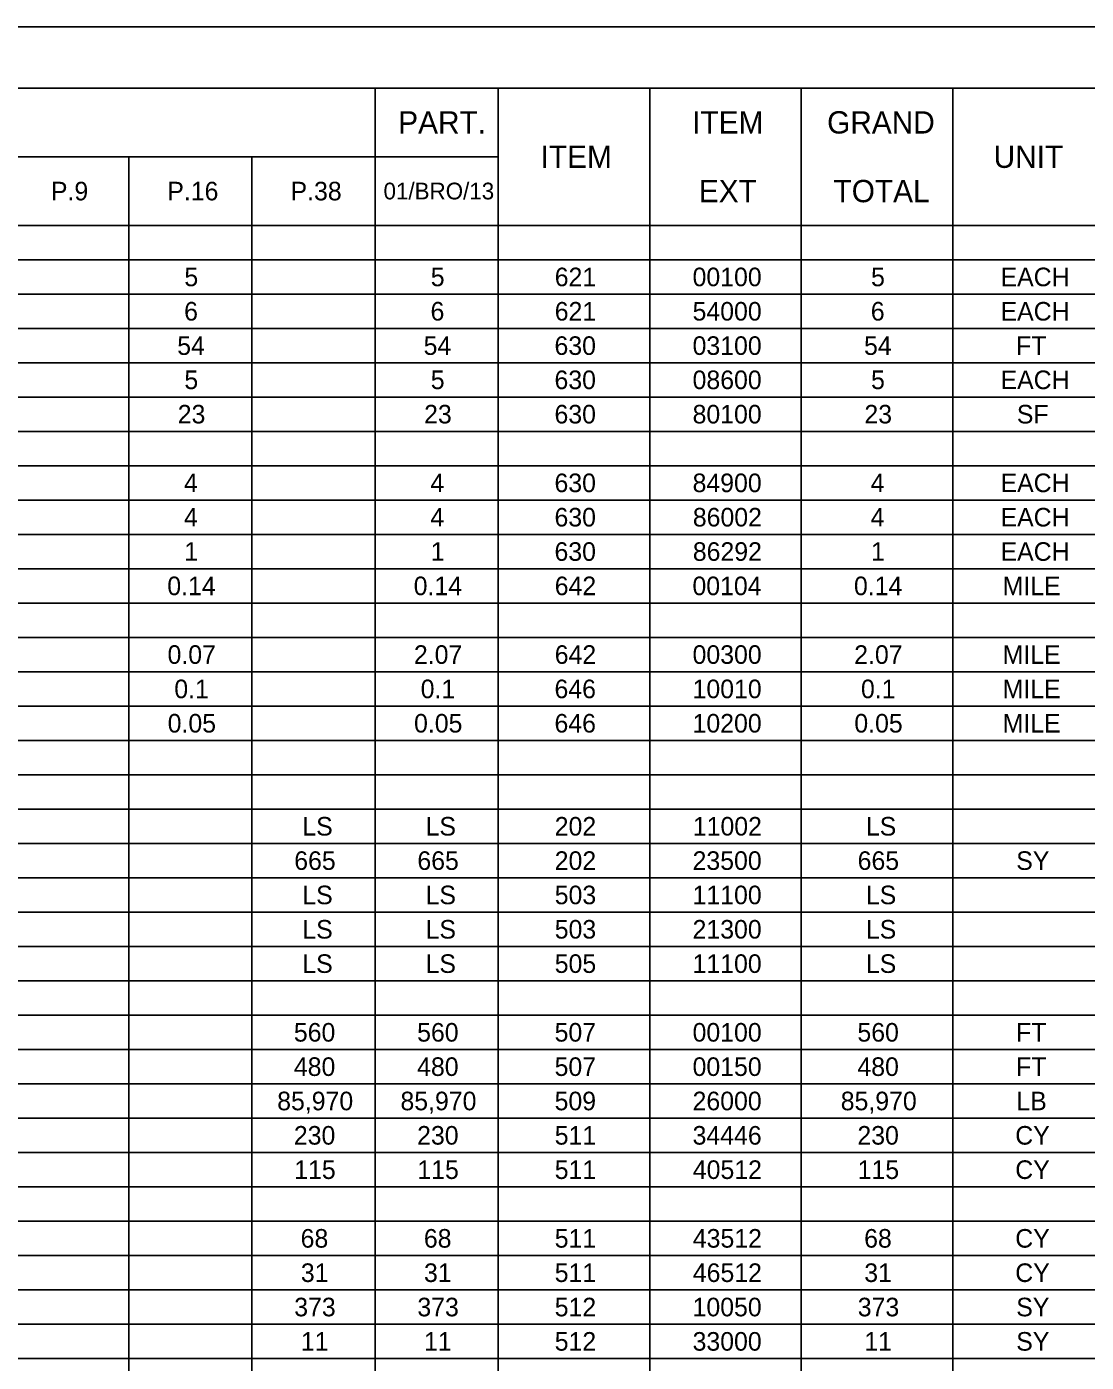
# Model space of a CAD drawing. Extents: x 0 to 34, y 0 to 22.
# Drawn here: x 8.71 to 17.35, y 11.11 to 22 of the extents above; entities that cross this region are included whole.
import ezdxf

# ---------------------------------------------------------------- set-up
doc = ezdxf.new("R2010")
doc.units = 0
for name, color, linetype in [('Default', 7, 'Continuous'), ('SH_Border', 7, 'Continuous'), ('SH_Cut_Line', 7, 'Continuous')]:
    doc.layers.add(name, color=color, linetype=linetype)

msp = doc.modelspace()

# ---------------------------------------------------------------- linework, layer by layer
at = {"layer": 'Default'}
for p, q in [((1.5, 21.5), (32, 21.5)), ((11.546, 21.5), (11.546, 0.502)), ((12.55, 21.5), (12.55, 0.502)), ((13.786, 21.5), (13.786, 0.502)), ((15.021, 21.5), (15.021, 0.502)), ((16.256, 21.5), (16.256, 0.502)), ((1.5, 20.94), (12.55, 20.94)), ((9.537, 20.94), (9.537, 0.502)), ((10.541, 20.94), (10.541, 0.502)), ((1.5, 20.38), (32, 20.38)), ((1.5, 20.1), (32, 20.1)), ((1.5, 19.82), (32, 19.82)), ((1.5, 19.54), (32, 19.54)), ((1.5, 19.26), (32, 19.26)), ((1.5, 18.98), (32, 18.98)), ((1.5, 18.7), (32, 18.7)), ((1.5, 18.42), (32, 18.42)), ((1.5, 18.14), (32, 18.14)), ((1.5, 17.86), (32, 17.86)), ((1.5, 17.58), (32, 17.58)), ((1.5, 17.3), (32, 17.3)), ((1.5, 17.021), (32, 17.021)), ((1.5, 16.741), (32, 16.741)), ((1.5, 16.461), (32, 16.461)), ((1.5, 16.181), (32, 16.181)), ((1.5, 15.901), (32, 15.901)), ((1.5, 15.621), (32, 15.621)), ((1.5, 15.341), (32, 15.341)), ((1.5, 15.061), (32, 15.061)), ((1.5, 14.781), (32, 14.781)), ((1.5, 14.501), (32, 14.501)), ((1.5, 14.221), (32, 14.221)), ((1.5, 13.941), (32, 13.941)), ((1.5, 13.661), (32, 13.661)), ((1.5, 13.381), (32, 13.381)), ((1.5, 13.101), (32, 13.101)), ((1.5, 12.821), (32, 12.821)), ((1.5, 12.541), (32, 12.541)), ((1.5, 12.261), (32, 12.261)), ((1.5, 11.981), (32, 11.981)), ((1.5, 11.701), (32, 11.701)), ((1.5, 11.421), (32, 11.421)), ((1.5, 11.141), (32, 11.141))]:
    msp.add_line(p, q, dxfattribs=at)
at = {"layer": 'SH_Border'}
msp.add_lwpolyline([(1.5, 21.5), (33.5, 21.5), (33.5, 0.5), (1.5, 0.5)], close=True, dxfattribs=at)
at = {"layer": 'SH_Cut_Line'}
msp.add_lwpolyline([(0, 0), (34, 0), (34, 22), (0, 22)], close=True, dxfattribs=at)

# ---------------------------------------------------------------- texts
at = {"layer": 'Default'}
for s, height, p in [('PART.', 0.1818, (11.735, 21.129)), ('ITEM', 0.1818, (14.132, 21.129)), ('GRAND', 0.1818, (15.232, 21.129)), ('ITEM', 0.1818, (12.896, 20.849)), ('UNIT', 0.1818, (16.59, 20.849)), ('P.9', 0.1515, (8.903, 20.584)), ('P.16', 0.1515, (9.852, 20.584)), ('P.38', 0.1515, (10.857, 20.584)), ('01/BRO/13', 0.1364, (11.615, 20.592)), ('EXT', 0.1818, (14.186, 20.569)), ('TOTAL', 0.1818, (15.284, 20.569)), ('621', 0.1515, (13.011, 19.884)), ('00100', 0.1515, (14.135, 19.884)), ('EACH', 0.1515, (16.646, 19.884)), ('5', 0.152, (9.991, 19.884)), ('5', 0.152, (12, 19.884)), ('5', 0.152, (15.59, 19.884)), ('6', 0.152, (9.989, 19.604)), ('6', 0.152, (11.998, 19.604)), ('621', 0.1515, (13.011, 19.604)), ('54000', 0.1515, (14.135, 19.604)), ('6', 0.152, (15.588, 19.604)), ('EACH', 0.1515, (16.646, 19.604)), ('54', 0.1515, (9.933, 19.324)), ('54', 0.1515, (11.942, 19.324)), ('630', 0.1515, (13.009, 19.324)), ('03100', 0.1515, (14.135, 19.324)), ('54', 0.1515, (15.533, 19.324)), ('FT', 0.1515, (16.773, 19.324)), ('5', 0.152, (9.991, 19.045)), ('5', 0.152, (12, 19.045)), ('630', 0.1515, (13.009, 19.045)), ('08600', 0.1515, (14.135, 19.045)), ('5', 0.152, (15.59, 19.045)), ('EACH', 0.1515, (16.646, 19.045)), ('23', 0.1515, (9.937, 18.765)), ('23', 0.1515, (11.946, 18.765)), ('630', 0.1515, (13.009, 18.765)), ('80100', 0.1515, (14.135, 18.765)), ('23', 0.1515, (15.536, 18.765)), ('SF', 0.1515, (16.779, 18.765)), ('4', 0.152, (9.988, 18.205)), ('4', 0.152, (11.997, 18.205)), ('630', 0.1515, (13.009, 18.205)), ('84900', 0.1515, (14.135, 18.205)), ('4', 0.152, (15.587, 18.205)), ('EACH', 0.1515, (16.646, 18.205)), ('630', 0.1515, (13.009, 17.925)), ('86002', 0.1515, (14.137, 17.925)), ('EACH', 0.1515, (16.646, 17.925)), ('4', 0.152, (9.988, 17.925)), ('4', 0.152, (11.997, 17.925)), ('4', 0.152, (15.587, 17.925)), ('1', 0.152, (9.99, 17.645)), ('1', 0.152, (12, 17.645)), ('630', 0.1515, (13.009, 17.645)), ('86292', 0.1515, (14.137, 17.645)), ('1', 0.152, (15.59, 17.645)), ('EACH', 0.1515, (16.646, 17.645)), ('0.14', 0.1515, (9.852, 17.365)), ('0.14', 0.1515, (11.861, 17.365)), ('642', 0.1515, (13.011, 17.365)), ('00104', 0.1515, (14.134, 17.365)), ('0.14', 0.1515, (15.451, 17.365)), ('MILE', 0.1515, (16.663, 17.365)), ('0.07', 0.1515, (9.854, 16.805)), ('2.07', 0.1515, (11.863, 16.805)), ('642', 0.1515, (13.011, 16.805)), ('00300', 0.1515, (14.135, 16.805)), ('2.07', 0.1515, (15.453, 16.805)), ('MILE', 0.1515, (16.663, 16.805)), ('0.1', 0.1515, (9.909, 16.525)), ('0.1', 0.1515, (11.918, 16.525)), ('646', 0.1515, (13.009, 16.525)), ('10010', 0.1515, (14.135, 16.525)), ('0.1', 0.1515, (15.508, 16.525)), ('MILE', 0.1515, (16.663, 16.525)), ('0.05', 0.1515, (9.855, 16.245)), ('0.05', 0.1515, (11.864, 16.245)), ('646', 0.1515, (13.009, 16.245)), ('10200', 0.1515, (14.135, 16.245)), ('0.05', 0.1515, (15.454, 16.245)), ('MILE', 0.1515, (16.663, 16.245)), ('LS', 0.1515, (10.953, 15.405)), ('LS', 0.1515, (11.958, 15.405)), ('202', 0.1515, (13.011, 15.405)), ('11002', 0.1515, (14.137, 15.405)), ('LS', 0.1515, (15.548, 15.405)), ('665', 0.1515, (10.887, 15.125)), ('665', 0.1515, (11.891, 15.125)), ('202', 0.1515, (13.011, 15.125)), ('23500', 0.1515, (14.135, 15.125)), ('665', 0.1515, (15.481, 15.125)), ('SY', 0.1515, (16.774, 15.125)), ('LS', 0.1515, (10.953, 14.845)), ('LS', 0.1515, (11.958, 14.845)), ('503', 0.1515, (13.011, 14.845)), ('11100', 0.1515, (14.135, 14.845)), ('LS', 0.1515, (15.548, 14.845)), ('LS', 0.1515, (10.953, 14.565)), ('LS', 0.1515, (11.958, 14.565)), ('503', 0.1515, (13.011, 14.565)), ('21300', 0.1515, (14.135, 14.565)), ('LS', 0.1515, (15.548, 14.565)), ('LS', 0.1515, (10.953, 14.285)), ('LS', 0.1515, (11.958, 14.285)), ('505', 0.1515, (13.011, 14.285)), ('11100', 0.1515, (14.135, 14.285)), ('LS', 0.1515, (15.548, 14.285)), ('560', 0.1515, (10.884, 13.725)), ('560', 0.1515, (11.889, 13.725)), ('507', 0.1515, (13.01, 13.725)), ('00100', 0.1515, (14.135, 13.725)), ('560', 0.1515, (15.479, 13.725)), ('FT', 0.1515, (16.773, 13.725)), ('480', 0.1515, (10.884, 13.445)), ('480', 0.1515, (11.889, 13.445)), ('507', 0.1515, (13.01, 13.445)), ('00150', 0.1515, (14.135, 13.445)), ('480', 0.1515, (15.479, 13.445)), ('FT', 0.1515, (16.773, 13.445)), ('85,970', 0.1515, (10.748, 13.165)), ('85,970', 0.1515, (11.753, 13.165)), ('509', 0.1515, (13.01, 13.165)), ('26000', 0.1515, (14.135, 13.165)), ('85,970', 0.1515, (15.343, 13.165)), ('LB', 0.1515, (16.775, 13.165)), ('230', 0.1515, (10.884, 12.885)), ('230', 0.1515, (11.889, 12.885)), ('511', 0.1515, (13.011, 12.885)), ('34446', 0.1515, (14.135, 12.885)), ('230', 0.1515, (15.479, 12.885)), ('CY', 0.1515, (16.766, 12.885)), ('115', 0.1515, (10.887, 12.605)), ('115', 0.1515, (11.891, 12.605)), ('511', 0.1515, (13.011, 12.605)), ('40512', 0.1515, (14.137, 12.605)), ('115', 0.1515, (15.481, 12.605)), ('CY', 0.1515, (16.766, 12.605)), ('68', 0.1515, (10.939, 12.045)), ('68', 0.1515, (11.944, 12.045)), ('511', 0.1515, (13.011, 12.045)), ('43512', 0.1515, (14.137, 12.045)), ('68', 0.1515, (15.534, 12.045)), ('CY', 0.1515, (16.766, 12.045)), ('31', 0.1515, (10.941, 11.765)), ('31', 0.1515, (11.945, 11.765)), ('511', 0.1515, (13.011, 11.765)), ('46512', 0.1515, (14.137, 11.765)), ('31', 0.1515, (15.535, 11.765)), ('CY', 0.1515, (16.766, 11.765)), ('373', 0.1515, (10.887, 11.485)), ('373', 0.1515, (11.891, 11.485)), ('512', 0.1515, (13.011, 11.485)), ('10050', 0.1515, (14.135, 11.485)), ('373', 0.1515, (15.482, 11.485)), ('SY', 0.1515, (16.774, 11.485)), ('11', 0.1515, (10.941, 11.205)), ('11', 0.1515, (11.945, 11.205)), ('512', 0.1515, (13.011, 11.205)), ('33000', 0.1515, (14.135, 11.205)), ('11', 0.1515, (15.535, 11.205)), ('SY', 0.1515, (16.774, 11.205))]:
    msp.add_text(s, height=height, dxfattribs=at).set_placement(p)

doc.saveas('drawing.dxf')
